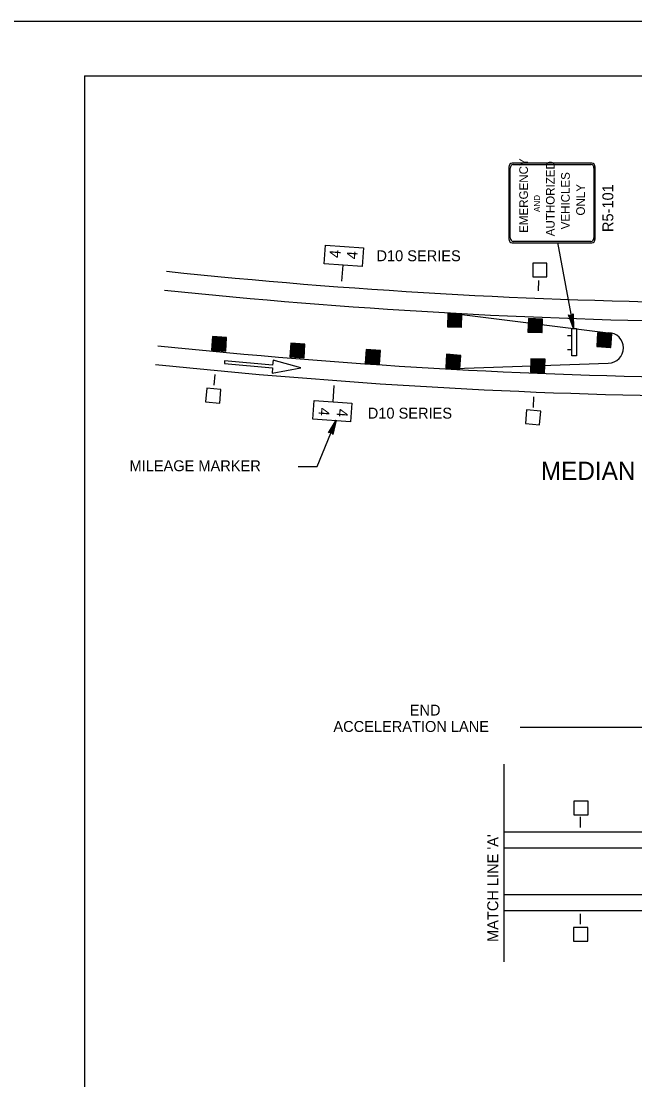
# Model space of a CAD drawing. Extents: x 640253 to 641999, y 298458 to 299646.
# Drawn here: x 641116.9 to 641285.7, y 299354.5 to 299645.6 of the extents above; entities that cross this region are included whole.
import ezdxf

# ---------------------------------------------------------------- set-up
doc = ezdxf.new("R2010")
doc.units = 0
for name, color, linetype in [('1', 7, 'Continuous'), ('2', 7, 'Continuous'), ('PLT-BNDY', 7, 'Continuous')]:
    doc.layers.add(name, color=color, linetype=linetype)

msp = doc.modelspace()

# ---------------------------------------------------------------- linework, layer by layer
at = {"layer": '1'}
for q in [(641920.31, 299630.63), (641134.31, 299066.63)]:
    msp.add_line((641134.31, 299630.63), q, dxfattribs=at)
at = {"layer": '2'}
for p, q in [((641250.99, 299605.5), (641250.99, 299585.75)), ((641251.34, 299586.08), (641251.34, 299605.18)), ((641273.81, 299606.6), (641251.94, 299606.6)), ((641252.22, 299606.19), (641273.53, 299606.19)), ((641274.41, 299605.18), (641274.41, 299586.08)), ((641274.77, 299585.75), (641274.77, 299605.5)), ((641251.94, 299584.66), (641273.81, 299584.66)), ((641273.53, 299585.06), (641252.22, 299585.06)), ((641205.09, 299574.16), (641205.4, 299578.5)), ((641259.12, 299571.43), (641259.24, 299574.31)), ((641234.43, 299565.41), (641278.36, 299559.94)), ((641268.37, 299559.11), (641267.12, 299559.11)), ((641268.37, 299555.26), (641267.12, 299555.26)), ((641172.82, 299552.2), (641172.75, 299551.49)), ((641172.75, 299551.49), (641186.02, 299550.28)), ((641186.01, 299550.99), (641172.82, 299552.2)), ((641186.02, 299550.28), (641185.89, 299548.84)), ((641185.89, 299548.84), (641193.78, 299550.25)), ((641186.14, 299552.43), (641186.01, 299550.99)), ((641193.78, 299550.25), (641186.14, 299552.43)), ((641233.6, 299550.02), (641278.36, 299551.58)), ((641169.98, 299545.5), (641170.21, 299548.48)), ((641202.9, 299545.44), (641202.58, 299540.96)), ((641257.76, 299539.4), (641257.89, 299542.27)), ((641308.68, 299451.35), (641254.07, 299451.35)), ((641249.69, 299386.92), (641249.69, 299441.25)), ((641270.73, 299423.91), (641270.73, 299426.76)), ((641249.69, 299422.63), (641308.69, 299422.63)), ((641249.69, 299418.29), (641619.6, 299418.29)), ((641249.69, 299405.41), (641548.4, 299405.41)), ((641249.69, 299401.07), (641390.19, 299401.07)), ((641270.73, 299397.25), (641270.73, 299400.1)), ((641275.73, 299401.07), (641275.73, 299401.07))]:
    msp.add_line(p, q, dxfattribs=at)
for points in [[(641264.39, 299584.73), (641268.78, 299561.09)], [(641234.08, 299561.57), (641237.98, 299561.43), (641238.11, 299565.17), (641234.22, 299565.31), (641234.08, 299561.57), (641238.05, 299565.11), (641234.28, 299565.24), (641234.15, 299561.62), (641237.92, 299561.48), (641238.05, 299565.04), (641234.36, 299565.17), (641234.23, 299561.68), (641237.84, 299561.56), (641237.95, 299564.96), (641234.42, 299565.08), (641234.3, 299561.74), (641237.78, 299561.62), (641237.9, 299564.9), (641234.48, 299565.02), (641234.37, 299561.79), (641237.7, 299561.68), (641237.81, 299564.83), (641234.55, 299564.95), (641234.43, 299561.85), (641237.64, 299561.76), (641237.72, 299564.76), (641234.62, 299564.87), (641234.5, 299561.91), (641237.57, 299561.83), (641237.66, 299564.7), (641234.68, 299564.8), (641234.56, 299561.99), (641237.49, 299561.91), (641237.58, 299564.61), (641234.77, 299564.72), (641234.64, 299562.04), (641237.39, 299561.99), (641237.49, 299564.55), (641234.84, 299564.65), (641234.71, 299562.1), (641237.32, 299562.05), (641237.4, 299564.5), (641234.92, 299564.57), (641234.8, 299562.14), (641237.23, 299562.12), (641237.3, 299564.42), (641235, 299564.47), (641234.92, 299563.37), (641234.88, 299562.21), (641237.16, 299562.2), (641237.2, 299564.33), (641235.08, 299564.36), (641234.96, 299562.28), (641237.07, 299562.28), (641237.11, 299564.26), (641235.18, 299564.26), (641235.08, 299562.36), (641236.95, 299562.35), (641236.99, 299564.13), (641235.31, 299564.15), (641235.2, 299562.48), (641236.81, 299562.46), (641236.84, 299564.03), (641235.46, 299564.02), (641235.34, 299562.6), (641235.35, 299562.6), (641236.66, 299562.6), (641236.7, 299563.89), (641235.59, 299563.89), (641235.49, 299562.72), (641236.51, 299562.74), (641236.56, 299563.74), (641235.73, 299563.75), (641235.66, 299562.87), (641236.36, 299562.87), (641236.36, 299563.62), (641235.89, 299563.6), (641235.85, 299563), (641236.19, 299563.02), (641236.21, 299563.47), (641236.06, 299563.5), (641236.03, 299563.14)], [(641268.55, 299564.9), (641268.32, 299564.71), (641268.78, 299561.09), (641268.55, 299564.9), (641268.68, 299565.11), (641268.78, 299561.09), (641267.94, 299564.63), (641267.65, 299564.71), (641268.78, 299561.09), (641267.43, 299564.88), (641267.65, 299564.71)], [(641256.24, 299560.1), (641260.14, 299559.96), (641260.27, 299563.7), (641256.37, 299563.84), (641256.24, 299560.1), (641260.2, 299563.63), (641256.44, 299563.77), (641256.31, 299560.14), (641260.08, 299560.01), (641260.2, 299563.57), (641256.51, 299563.7), (641256.38, 299560.21), (641260, 299560.08), (641260.11, 299563.48), (641256.57, 299563.61), (641256.46, 299560.27), (641259.93, 299560.14), (641260.05, 299563.43), (641256.64, 299563.55), (641256.53, 299560.32), (641259.86, 299560.21), (641259.96, 299563.36), (641256.71, 299563.47), (641256.59, 299560.38), (641259.79, 299560.29), (641259.88, 299563.29), (641256.77, 299563.4), (641256.66, 299560.44), (641259.73, 299560.35), (641259.81, 299563.22), (641256.83, 299563.33), (641256.72, 299560.52), (641259.64, 299560.44), (641259.74, 299563.14), (641256.92, 299563.24), (641256.79, 299560.56), (641259.55, 299560.52), (641259.65, 299563.08), (641257, 299563.17), (641256.87, 299560.63), (641259.47, 299560.58), (641259.56, 299563.02), (641257.07, 299563.09), (641256.95, 299560.67), (641259.38, 299560.65), (641259.46, 299562.95), (641257.16, 299563), (641257.07, 299561.9), (641257.03, 299560.74), (641259.31, 299560.73), (641259.36, 299562.86), (641257.23, 299562.89), (641257.12, 299560.81), (641259.23, 299560.8), (641259.27, 299562.78), (641257.33, 299562.79), (641257.23, 299560.89), (641259.1, 299560.87), (641259.15, 299562.66), (641257.47, 299562.68), (641257.35, 299561.01), (641258.96, 299560.99), (641258.99, 299562.56), (641257.62, 299562.55), (641257.49, 299561.12), (641257.5, 299561.12), (641258.82, 299561.13), (641258.85, 299562.41), (641257.75, 299562.41), (641257.64, 299561.25), (641258.67, 299561.27), (641258.71, 299562.26), (641257.88, 299562.27), (641257.81, 299561.4), (641258.52, 299561.4), (641258.51, 299562.14), (641258.05, 299562.13), (641258.01, 299561.53), (641258.34, 299561.55), (641258.36, 299561.99), (641258.22, 299562.03), (641258.18, 299561.67)], [(641169.23, 299555.17), (641173.12, 299554.9), (641173.38, 299558.64), (641169.49, 299558.91), (641169.23, 299555.17), (641173.31, 299558.57), (641169.55, 299558.84), (641169.3, 299555.22), (641173.06, 299554.96), (641173.31, 299558.51), (641169.62, 299558.76), (641169.38, 299555.28), (641172.98, 299555.03), (641173.21, 299558.42), (641169.68, 299558.67), (641169.45, 299555.34), (641172.92, 299555.09), (641173.15, 299558.37), (641169.75, 299558.61), (641169.52, 299555.39), (641172.85, 299555.16), (641173.06, 299558.31), (641169.81, 299558.54), (641169.58, 299555.45), (641172.79, 299555.24), (641172.98, 299558.24), (641169.88, 299558.46), (641169.66, 299555.51), (641172.72, 299555.31), (641172.91, 299558.17), (641169.94, 299558.38), (641169.72, 299555.58), (641172.64, 299555.4), (641172.83, 299558.09), (641170.02, 299558.3), (641169.8, 299555.62), (641172.55, 299555.48), (641172.74, 299558.04), (641170.09, 299558.22), (641169.88, 299555.69), (641172.48, 299555.55), (641172.65, 299557.99), (641170.17, 299558.14), (641169.96, 299555.72), (641172.39, 299555.62), (641172.54, 299557.92), (641170.25, 299558.04), (641170.12, 299556.95), (641170.04, 299555.79), (641172.32, 299555.7), (641172.44, 299557.82), (641170.32, 299557.93), (641170.13, 299555.85), (641172.24, 299555.78), (641172.34, 299557.75), (641170.42, 299557.83), (641170.24, 299555.93), (641172.11, 299555.85), (641172.22, 299557.63), (641170.55, 299557.71), (641170.37, 299556.05), (641171.98, 299555.97), (641172.07, 299557.54), (641170.69, 299557.58), (641170.52, 299556.16), (641170.52, 299556.16), (641171.84, 299556.12), (641171.92, 299557.4), (641170.82, 299557.44), (641170.67, 299556.28), (641171.7, 299556.27), (641171.77, 299557.26), (641170.95, 299557.3), (641170.85, 299556.42), (641171.55, 299556.4), (641171.57, 299557.14), (641171.1, 299557.15), (641171.04, 299556.55), (641171.38, 299556.55), (641171.41, 299557), (641171.27, 299557.04), (641171.22, 299556.68)], [(641275.16, 299556.14), (641279.05, 299555.86), (641279.31, 299559.6), (641275.42, 299559.87), (641275.16, 299556.14), (641279.24, 299559.53), (641275.48, 299559.8), (641275.23, 299556.18), (641278.99, 299555.92), (641279.24, 299559.46), (641275.55, 299559.72), (641275.31, 299556.24), (641278.92, 299555.99), (641279.15, 299559.38), (641275.62, 299559.63), (641275.38, 299556.29), (641278.85, 299556.05), (641279.08, 299559.33), (641275.68, 299559.57), (641275.46, 299556.35), (641278.78, 299556.12), (641278.99, 299559.26), (641275.74, 299559.49), (641275.52, 299556.4), (641278.72, 299556.2), (641278.91, 299559.2), (641275.81, 299559.41), (641275.59, 299556.47), (641278.65, 299556.27), (641278.84, 299559.13), (641275.87, 299559.34), (641275.65, 299556.54), (641278.57, 299556.36), (641278.76, 299559.05), (641275.95, 299559.25), (641275.73, 299556.58), (641278.48, 299556.44), (641278.67, 299559), (641276.02, 299559.18), (641275.81, 299556.65), (641278.41, 299556.5), (641278.58, 299558.94), (641276.09, 299559.1), (641275.89, 299556.68), (641278.32, 299556.58), (641278.47, 299558.87), (641276.18, 299559), (641276.05, 299557.91), (641275.97, 299556.74), (641278.25, 299556.66), (641278.37, 299558.78), (641276.25, 299558.89), (641276.06, 299556.81), (641278.17, 299556.74), (641278.28, 299558.71), (641276.35, 299558.79), (641276.18, 299556.89), (641278.05, 299556.81), (641278.15, 299558.59), (641276.48, 299558.67), (641276.3, 299557.01), (641277.91, 299556.93), (641278, 299558.5), (641276.62, 299558.53), (641276.45, 299557.12), (641276.46, 299557.12), (641277.77, 299557.07), (641277.85, 299558.36), (641276.75, 299558.4), (641276.6, 299557.24), (641277.62, 299557.22), (641277.71, 299558.21), (641276.88, 299558.26), (641276.78, 299557.38), (641277.48, 299557.36), (641277.5, 299558.1), (641277.03, 299558.1), (641276.97, 299557.51), (641277.31, 299557.51), (641277.34, 299557.96), (641277.2, 299558), (641277.16, 299557.64)], [(641190.77, 299553.3), (641194.66, 299553.02), (641194.92, 299556.76), (641191.03, 299557.03), (641190.77, 299553.3), (641194.85, 299556.7), (641191.09, 299556.96), (641190.84, 299553.34), (641194.6, 299553.08), (641194.84, 299556.63), (641191.16, 299556.89), (641190.92, 299553.4), (641194.52, 299553.15), (641194.75, 299556.55), (641191.22, 299556.79), (641190.99, 299553.46), (641194.46, 299553.22), (641194.69, 299556.49), (641191.29, 299556.73), (641191.06, 299553.51), (641194.39, 299553.29), (641194.6, 299556.43), (641191.35, 299556.66), (641191.12, 299553.57), (641194.33, 299553.36), (641194.51, 299556.36), (641191.41, 299556.58), (641191.2, 299553.63), (641194.26, 299553.43), (641194.44, 299556.3), (641191.48, 299556.51), (641191.26, 299553.7), (641194.18, 299553.52), (641194.37, 299556.21), (641191.56, 299556.42), (641191.33, 299553.75), (641194.09, 299553.6), (641194.27, 299556.16), (641191.63, 299556.34), (641191.42, 299553.81), (641194.01, 299553.67), (641194.18, 299556.11), (641191.7, 299556.26), (641191.5, 299553.84), (641193.93, 299553.74), (641194.08, 299556.04), (641191.79, 299556.17), (641191.66, 299555.07), (641191.58, 299553.91), (641193.86, 299553.82), (641193.98, 299555.95), (641191.86, 299556.06), (641191.67, 299553.98), (641193.77, 299553.9), (641193.88, 299555.88), (641191.96, 299555.95), (641191.78, 299554.06), (641193.65, 299553.97), (641193.76, 299555.76), (641192.08, 299555.84), (641191.91, 299554.17), (641193.52, 299554.09), (641193.61, 299555.66), (641192.23, 299555.7), (641192.06, 299554.28), (641192.06, 299554.28), (641193.38, 299554.24), (641193.46, 299555.52), (641192.36, 299555.56), (641192.21, 299554.4), (641193.23, 299554.39), (641193.31, 299555.38), (641192.49, 299555.42), (641192.38, 299554.54), (641193.09, 299554.52), (641193.11, 299555.26), (641192.64, 299555.27), (641192.58, 299554.67), (641192.92, 299554.67), (641192.95, 299555.12), (641192.81, 299555.16), (641192.76, 299554.8)], [(641211.51, 299551.56), (641215.4, 299551.29), (641215.66, 299555.02), (641211.77, 299555.29), (641211.51, 299551.56), (641215.59, 299554.95), (641211.84, 299555.22), (641211.58, 299551.6), (641215.34, 299551.34), (641215.59, 299554.89), (641211.91, 299555.15), (641211.66, 299551.66), (641215.27, 299551.41), (641215.5, 299554.81), (641211.97, 299555.05), (641211.73, 299551.72), (641215.21, 299551.48), (641215.43, 299554.75), (641212.03, 299554.99), (641211.81, 299551.77), (641215.13, 299551.55), (641215.34, 299554.69), (641212.1, 299554.92), (641211.87, 299551.83), (641215.07, 299551.62), (641215.26, 299554.62), (641212.16, 299554.84), (641211.94, 299551.89), (641215.01, 299551.69), (641215.19, 299554.56), (641212.22, 299554.77), (641212.01, 299551.96), (641214.92, 299551.78), (641215.11, 299554.47), (641212.31, 299554.68), (641212.08, 299552.01), (641214.83, 299551.86), (641215.02, 299554.42), (641212.38, 299554.61), (641212.16, 299552.07), (641214.76, 299551.93), (641214.93, 299554.37), (641212.45, 299554.52), (641212.24, 299552.11), (641214.68, 299552), (641214.83, 299554.3), (641212.53, 299554.43), (641212.41, 299553.33), (641212.32, 299552.17), (641214.6, 299552.09), (641214.73, 299554.21), (641212.6, 299554.32), (641212.42, 299552.24), (641214.52, 299552.16), (641214.63, 299554.14), (641212.7, 299554.21), (641212.53, 299552.32), (641214.4, 299552.23), (641214.51, 299554.02), (641212.83, 299554.1), (641212.66, 299552.44), (641214.26, 299552.35), (641214.35, 299553.92), (641212.98, 299553.96), (641212.8, 299552.54), (641212.81, 299552.54), (641214.13, 299552.5), (641214.21, 299553.79), (641213.11, 299553.82), (641212.95, 299552.66), (641213.98, 299552.65), (641214.06, 299553.64), (641213.23, 299553.68), (641213.13, 299552.8), (641213.83, 299552.78), (641213.86, 299553.52), (641213.39, 299553.53), (641213.32, 299552.93), (641213.67, 299552.93), (641213.7, 299553.38), (641213.55, 299553.42), (641213.51, 299553.06)], [(641233.63, 299550.26), (641237.52, 299549.99), (641237.78, 299553.72), (641233.89, 299554), (641233.63, 299550.26), (641237.72, 299553.66), (641233.96, 299553.92), (641233.7, 299550.31), (641237.46, 299550.04), (641237.71, 299553.6), (641234.03, 299553.85), (641233.78, 299550.37), (641237.39, 299550.12), (641237.62, 299553.51), (641234.09, 299553.76), (641233.85, 299550.42), (641237.33, 299550.18), (641237.56, 299553.46), (641234.15, 299553.7), (641233.93, 299550.48), (641237.26, 299550.25), (641237.46, 299553.4), (641234.22, 299553.62), (641233.99, 299550.53), (641237.19, 299550.33), (641237.38, 299553.33), (641234.28, 299553.55), (641234.06, 299550.6), (641237.13, 299550.4), (641237.31, 299553.26), (641234.34, 299553.47), (641234.13, 299550.67), (641237.05, 299550.49), (641237.23, 299553.18), (641234.42, 299553.39), (641234.2, 299550.71), (641236.95, 299550.57), (641237.14, 299553.13), (641234.5, 299553.31), (641234.28, 299550.77), (641236.88, 299550.63), (641237.05, 299553.07), (641234.57, 299553.23), (641234.36, 299550.81), (641236.8, 299550.71), (641236.95, 299553.01), (641234.65, 299553.13), (641234.52, 299552.04), (641234.44, 299550.87), (641236.72, 299550.79), (641236.84, 299552.91), (641234.72, 299553.02), (641234.54, 299550.94), (641236.64, 299550.86), (641236.75, 299552.84), (641234.82, 299552.92), (641234.65, 299551.02), (641236.52, 299550.94), (641236.62, 299552.72), (641234.95, 299552.8), (641234.77, 299551.14), (641236.38, 299551.06), (641236.47, 299552.63), (641235.09, 299552.66), (641234.92, 299551.25), (641234.93, 299551.25), (641236.25, 299551.21), (641236.32, 299552.49), (641235.22, 299552.53), (641235.07, 299551.37), (641236.1, 299551.35), (641236.18, 299552.35), (641235.35, 299552.38), (641235.25, 299551.51), (641235.95, 299551.49), (641235.98, 299552.23), (641235.51, 299552.24), (641235.45, 299551.64), (641235.79, 299551.64), (641235.82, 299552.09), (641235.67, 299552.12), (641235.63, 299551.77)], [(641256.92, 299549.05), (641260.82, 299548.91), (641260.95, 299552.65), (641257.05, 299552.79), (641256.92, 299549.05), (641260.88, 299552.59), (641257.12, 299552.71), (641256.99, 299549.09), (641260.76, 299548.96), (641260.88, 299552.52), (641257.19, 299552.65), (641257.07, 299549.16), (641260.68, 299549.03), (641260.79, 299552.43), (641257.25, 299552.55), (641257.14, 299549.21), (641260.61, 299549.09), (641260.73, 299552.38), (641257.32, 299552.49), (641257.21, 299549.27), (641260.54, 299549.16), (641260.64, 299552.31), (641257.39, 299552.42), (641257.27, 299549.33), (641260.47, 299549.23), (641260.56, 299552.24), (641257.45, 299552.35), (641257.34, 299549.39), (641260.41, 299549.3), (641260.49, 299552.17), (641257.51, 299552.27), (641257.4, 299549.47), (641260.32, 299549.39), (641260.42, 299552.09), (641257.6, 299552.19), (641257.47, 299549.51), (641260.23, 299549.47), (641260.32, 299552.03), (641257.68, 299552.12), (641257.55, 299549.58), (641260.15, 299549.53), (641260.24, 299551.97), (641257.75, 299552.04), (641257.63, 299549.62), (641260.06, 299549.6), (641260.14, 299551.9), (641257.84, 299551.95), (641257.75, 299550.85), (641257.71, 299549.68), (641259.99, 299549.68), (641260.03, 299551.81), (641257.91, 299551.84), (641257.8, 299549.76), (641259.91, 299549.75), (641259.95, 299551.73), (641258.01, 299551.74), (641257.91, 299549.84), (641259.78, 299549.82), (641259.82, 299551.61), (641258.15, 299551.63), (641258.03, 299549.96), (641259.64, 299549.94), (641259.67, 299551.5), (641258.3, 299551.49), (641258.17, 299550.07), (641258.18, 299550.07), (641259.5, 299550.08), (641259.53, 299551.37), (641258.43, 299551.36), (641258.32, 299550.2), (641259.34, 299550.22), (641259.39, 299551.21), (641258.56, 299551.22), (641258.49, 299550.35), (641259.2, 299550.35), (641259.19, 299551.09), (641258.73, 299551.08), (641258.68, 299550.48), (641259.02, 299550.5), (641259.04, 299550.94), (641258.9, 299550.97), (641258.86, 299550.62)], [(641193.09, 299523.13), (641198.3, 299523.13), (641203.52, 299535.88)], [(641201.65, 299532.57), (641201.96, 299532.59), (641203.52, 299535.88), (641201.65, 299532.57), (641201.42, 299532.44), (641203.52, 299535.88), (641202.32, 299532.44), (641202.5, 299532.21), (641203.52, 299535.88), (641202.61, 299531.96), (641202.5, 299532.21)]]:
    msp.add_lwpolyline(points, dxfattribs=at)
for points in [[(641200.23, 299578.87), (641200.61, 299584.06), (641211, 299583.31), (641210.63, 299578.12)], [(641257.58, 299575.31), (641261.48, 299575.31), (641261.48, 299579.06), (641257.58, 299579.06)], [(641268.35, 299553.59), (641268.35, 299561.09), (641269.6, 299561.09), (641269.6, 299553.59)], [(641167.6, 299540.91), (641171.48, 299540.57), (641171.81, 299544.31), (641167.93, 299544.65)], [(641207.84, 299540.59), (641207.46, 299535.4), (641197.07, 299536.15), (641197.44, 299541.34)], [(641255.55, 299534.97), (641259.43, 299534.63), (641259.76, 299538.36), (641255.88, 299538.71)], [(641268.89, 299427.36), (641272.79, 299427.36), (641272.79, 299431.11), (641268.89, 299431.11)], [(641268.79, 299392.6), (641272.69, 299392.6), (641272.69, 299396.35), (641268.79, 299396.35)]]:
    msp.add_lwpolyline(points, close=True, dxfattribs=at)
for centre, radius, start, end in [((641324.62, 301181.29), 1613.21, 264.03084, 274.7698), ((641324.62, 301181.29), 1618.4, 264.02808, 274.75447), ((641278.36, 299555.77), 4.17, 270, 90), ((641324.62, 301181.29), 1633.8, 264.01999, 274.70955), ((641324.62, 301181.29), 1638.99, 264.0173, 274.6946)]:
    msp.add_arc(centre, radius, start, end, dxfattribs=at)
for centre, major_axis, start_param, end_param in [((641251.94, 299605.5), (0, -1.1), 3.141593, 4.712389), ((641252.22, 299605.18), (0, -1.01), 3.141593, 4.712389), ((641273.53, 299605.18), (0, 1.01), 4.712389, 6.283185), ((641273.81, 299605.5), (0, 1.1), 4.712389, 6.283185), ((641251.94, 299585.75), (0, -1.1), 4.712389, 6.283185), ((641252.22, 299586.08), (0, -1.01), 4.712389, 6.283185), ((641273.53, 299586.08), (0, 1.01), 3.141593, 4.712389), ((641273.81, 299585.75), (0, 1.1), 3.141593, 4.712389)]:
    msp.add_ellipse(centre, major_axis=major_axis, ratio=0.866667, start_param=start_param, end_param=end_param, dxfattribs=at)
at = {"layer": 'PLT-BNDY'}
msp.add_lwpolyline([(641094.31, 299645.63), (641935.31, 299645.63), (641935.31, 299051.63), (641094.31, 299051.63)], close=True, dxfattribs=at)

# ---------------------------------------------------------------- texts
at = {"layer": '2'}
for s, height, rotation, p in [('EMERGENCY', 2.377, 90, (641256.24, 299587.41)), ('AUTHORIZED', 2.377, 90, (641263.59, 299586.47)), ('VEHICLES', 2.377, 90, (641267.75, 299588.38)), ('ONLY', 2.377, 90, (641271.91, 299592.17)), ('R5-101', 3, 90, (641279.73, 299587.63)), ('AND', 1.664, 90, (641259.56, 299593.13)), ('4', 3, 85.8569, (641204.62, 299580.41)), ('4', 3, 85.8569, (641209.33, 299580.07)), ('4', 3, 265.8569, (641198.77, 299539.41)), ('4', 3, 265.8569, (641203.77, 299539.09)), ("MATCH LINE 'A'", 3, 90, (641248.07, 299392.38))]:
    msp.add_text(s, height=height, rotation=rotation, dxfattribs=at).set_placement(p)
for s, height, p in [('D10 SERIES', 3, (641214.58, 299579.61)), ('D10 SERIES', 3, (641212.19, 299536.32)), ('MILEAGE MARKER', 3, (641146.66, 299521.85)), ('MEDIAN CROSSOVER', 5, (641259.81, 299519.47)), ('END', 3, (641223.73, 299454.65)), ('ACCELERATION LANE', 3, (641202.74, 299450.15))]:
    msp.add_text(s, height=height, dxfattribs=at).set_placement(p)

doc.saveas('drawing.dxf')
